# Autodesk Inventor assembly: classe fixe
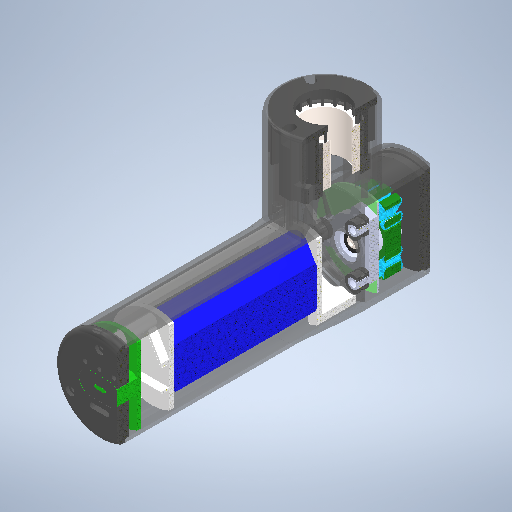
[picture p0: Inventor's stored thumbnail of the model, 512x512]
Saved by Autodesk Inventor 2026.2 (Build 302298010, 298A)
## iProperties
Created: 1601-01
Part Number: classe fixe
Document SubType Name: Assembly
Designer: mel
Part Number: Appareil_de_massage
Sending System: SOLIDWORKS 2023
Last Saved Date: 2025-04-02
Author: mel
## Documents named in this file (13)
- C:\Users\mel\Downloads\18256-itec-20250709t050547z-1-001 (1)\ITEC\Ressources\ITEC00_SW_Appareil_de_massage\S1Appareil_de_massage\S1Appareil_de_massage\classe fixe.iam
- C:\Users\mel\Downloads\18256-itec-20250709t050547z-1-001 (1)\ITEC\Ressources\ITEC00_SW_Appareil_de_massage\S1Appareil_de_massage\S1Appareil_de_massage\S1Bati.ipt
- C:\Users\mel\Downloads\18256-itec-20250709t050547z-1-001 (1)\ITEC\Ressources\ITEC00_SW_Appareil_de_massage\S1Appareil_de_massage\S1Appareil_de_massage\S1Capot_Haut.ipt
- C:\Users\mel\Downloads\18256-itec-20250709t050547z-1-001 (1)\ITEC\Ressources\ITEC00_SW_Appareil_de_massage\S1Appareil_de_massage\S1Appareil_de_massage\S1Support_Chemise.ipt
- C:\Users\mel\Downloads\18256-itec-20250709t050547z-1-001 (1)\ITEC\Ressources\ITEC00_SW_Appareil_de_massage\S1Appareil_de_massage\S1Appareil_de_massage\S1Chemise.ipt
- C:\Users\mel\Downloads\18256-itec-20250709t050547z-1-001 (1)\ITEC\Ressources\ITEC00_SW_Appareil_de_massage\S1Appareil_de_massage\S1Appareil_de_massage\S1Cylindre_bloc.ipt
- C:\Users\mel\Downloads\18256-itec-20250709t050547z-1-001 (1)\ITEC\Ressources\ITEC00_SW_Appareil_de_massage\S1Appareil_de_massage\S1Appareil_de_massage\S1BrushlessStator_Moteur.ipt
- C:\Users\mel\Downloads\18256-itec-20250709t050547z-1-001 (1)\ITEC\Ressources\ITEC00_SW_Appareil_de_massage\S1Appareil_de_massage\S1Appareil_de_massage\S1BrushlessStator Assembly.iam
- C:\Users\mel\Downloads\18256-itec-20250709t050547z-1-001 (1)\ITEC\Ressources\ITEC00_SW_Appareil_de_massage\S1Appareil_de_massage\S1Appareil_de_massage\S1Capot_moteur.ipt
- C:\Users\mel\Downloads\18256-itec-20250709t050547z-1-001 (1)\ITEC\Ressources\ITEC00_SW_Appareil_de_massage\S1Appareil_de_massage\S1Appareil_de_massage\S1Support_Batterie.ipt
- C:\Users\mel\Downloads\18256-itec-20250709t050547z-1-001 (1)\ITEC\Ressources\ITEC00_SW_Appareil_de_massage\S1Appareil_de_massage\S1Appareil_de_massage\S1Batterie.ipt
- C:\Users\mel\Downloads\18256-itec-20250709t050547z-1-001 (1)\ITEC\Ressources\ITEC00_SW_Appareil_de_massage\S1Appareil_de_massage\S1Appareil_de_massage\S1Capot_Batterie.ipt
- C:\Users\mel\Downloads\18256-itec-20250709t050547z-1-001 (1)\ITEC\Ressources\ITEC00_SW_Appareil_de_massage\S1Appareil_de_massage\S1Appareil_de_massage\S1Carte_electronique.ipt
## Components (14 placed, 14 different names)
1. Bati-1
2. Capot_Haut-1
3. Support_Chemise-1
4. Chemise-1
5. Cylindre_bloc-1
6. Cylindre_bloc-2
7. Cylindre_bloc-3
8. BrushlessStator_Moteur-2
9. BrushlessStator Assembly-2 [sub-assembly]
10. Capot_moteur-1
11. Support_Batterie-1
12. Batterie-1
13. Capot_Batterie-1
14. Carte_electronique-1
